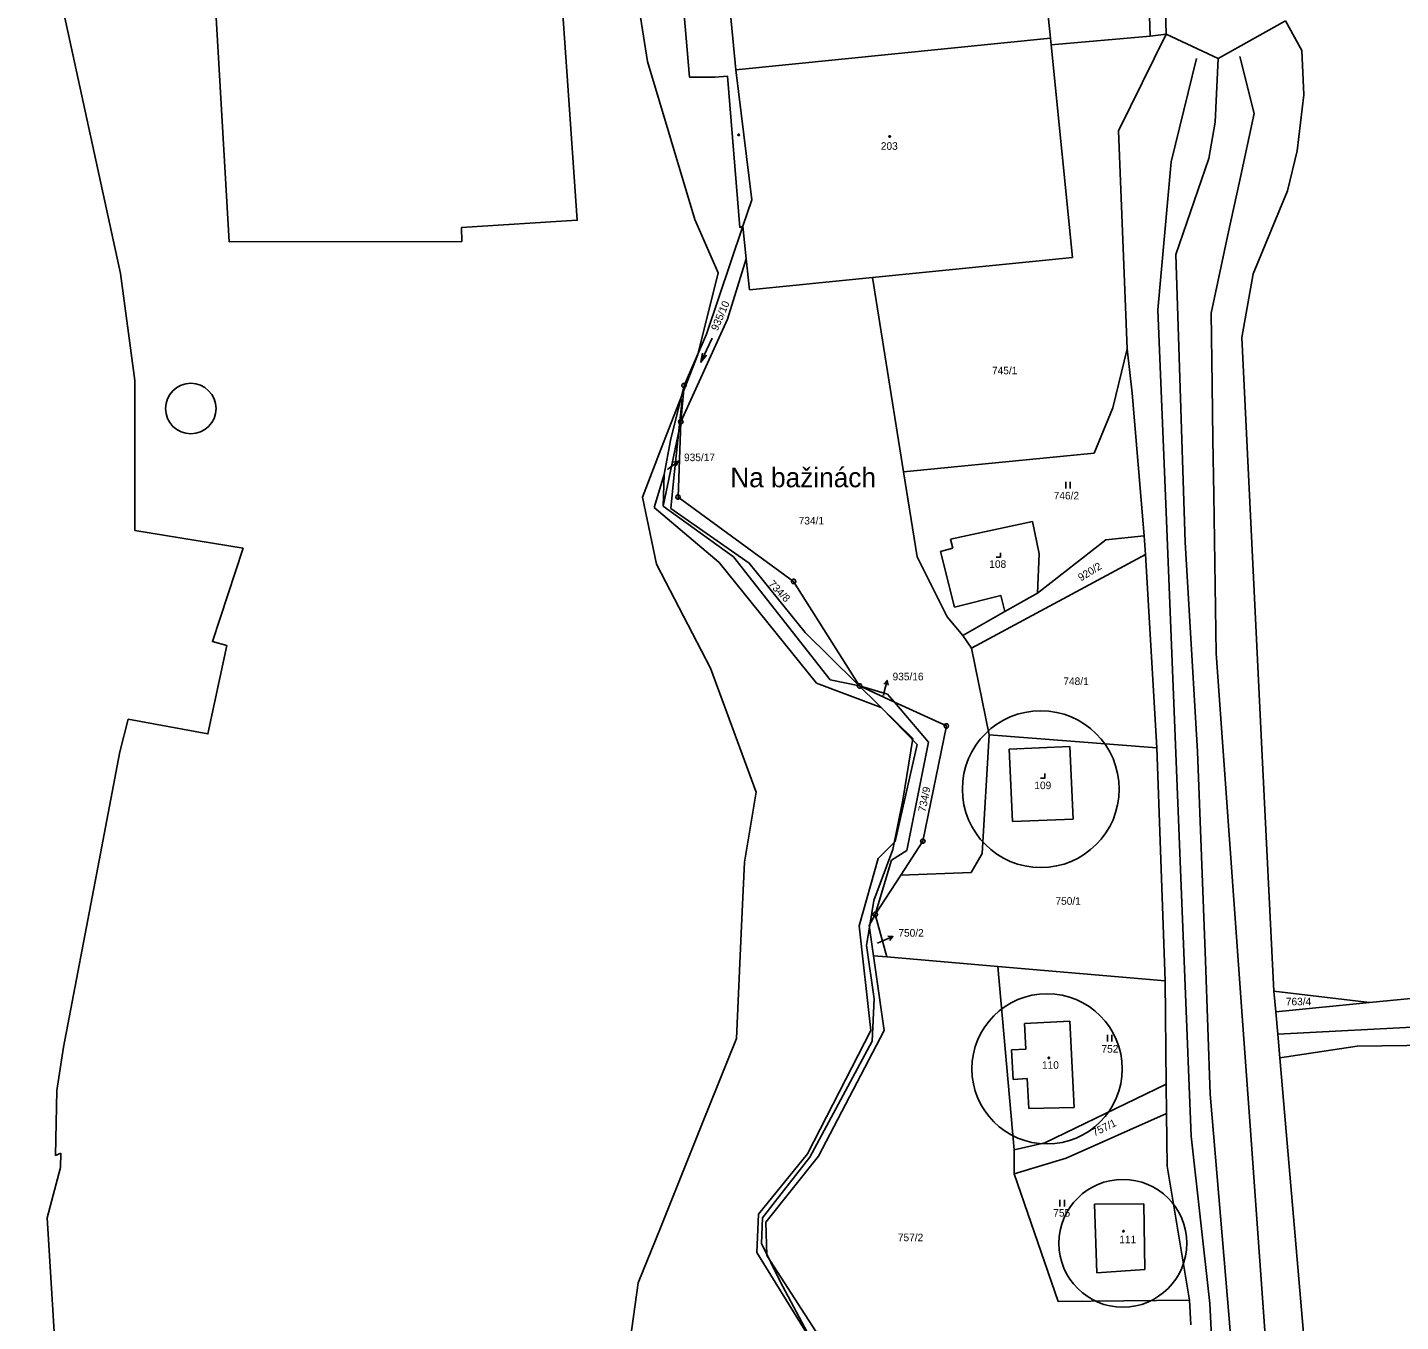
# Model space of a CAD drawing. Extents: x -580551 to -575069, y -1073031 to -1067931.
# Drawn here: x -578671.5 to -578363.2, y -1071557 to -1071266.5 of the extents above; entities that cross this region are included whole.
import ezdxf

# ---------------------------------------------------------------- set-up
doc = ezdxf.new("R2010")
doc.units = 0
for name, color, linetype in [('Druh pozemku', 7, 'Continuous'), ('Geodetické body', 7, 'Continuous'), ('Hranice státní', 7, 'Continuous'), ('Hranice z rastru', 7, 'Continuous'), ('Katastrální hranice', 7, 'Continuous'), ('Názvosloví', 7, 'Continuous'), ('Parcela', 7, 'Continuous'), ('Parcelní číslo', 7, 'Continuous'), ('Parcelní číslo_stavba', 7, 'Continuous'), ('Pomocná vrstva', 7, 'Continuous'), ('SR - hranice státu', 7, 'Continuous'), ('stavební parcely', 7, 'Continuous')]:
    doc.layers.add(name, color=color, linetype=linetype)

msp = doc.modelspace()

# ---------------------------------------------------------------- linework, layer by layer
at = {"layer": 'Druh pozemku'}
for p, q in [((-578517.744, -1071336.265), (-578520.296, -1071341.695)), ((-578438.37, -1071368.5), (-578438.37, -1071370)), ((-578437.37, -1071370), (-578437.37, -1071368.5)), ((-578429.01, -1071492.7), (-578429.01, -1071494.2)), ((-578428.01, -1071494.2), (-578428.01, -1071492.7)), ((-578439.7, -1071529.68), (-578439.7, -1071531.18)), ((-578438.7, -1071531.18), (-578438.7, -1071529.68))]:
    msp.add_line(p, q, dxfattribs=at)
for points in [[(-578511.72, -1071290.49), (-578511.63, -1071290.64), (-578511.72, -1071290.79), (-578511.9, -1071290.79), (-578511.99, -1071290.64), (-578511.9, -1071290.49)], [(-578477.81, -1071290.85), (-578477.72, -1071291), (-578477.81, -1071291.15), (-578477.99, -1071291.15), (-578478.08, -1071291), (-578477.99, -1071290.85)], [(-578442.1, -1071497.72), (-578442.01, -1071497.87), (-578442.1, -1071498.02), (-578442.28, -1071498.02), (-578442.37, -1071497.87), (-578442.28, -1071497.72)], [(-578425.35, -1071536.61), (-578425.26, -1071536.76), (-578425.35, -1071536.91), (-578425.53, -1071536.91), (-578425.62, -1071536.76), (-578425.53, -1071536.61)]]:
    msp.add_lwpolyline(points, close=True, dxfattribs=at)
for points in [[(-578518.993, -1071340.098), (-578520.296, -1071341.695), (-578519.898, -1071339.672)], [(-578454.04, -1071385.44), (-578453.04, -1071385.44), (-578453.04, -1071384.44)], [(-578444.05, -1071435.02), (-578443.05, -1071435.02), (-578443.05, -1071434.02)]]:
    msp.add_lwpolyline(points, dxfattribs=at)
at = {"layer": 'Geodetické body'}
for p, q in [((-578524.19, -1071346.92), (-578523.95, -1071346.92)), ((-578524.91, -1071355.06), (-578524.67, -1071355.06)), ((-578525.52, -1071371.95), (-578525.28, -1071371.95)), ((-578499.59, -1071390.89), (-578499.35, -1071390.89)), ((-578484.79, -1071414.36), (-578484.55, -1071414.36)), ((-578465.29, -1071423.34), (-578465.05, -1071423.34)), ((-578470.58, -1071449.22), (-578470.34, -1071449.22)), ((-578481.27, -1071465.65), (-578481.03, -1071465.65))]:
    msp.add_line(p, q, dxfattribs=at)
for points in [[(-578523.92, -1071346.44), (-578523.67, -1071346.62), (-578523.57, -1071346.91), (-578523.67, -1071347.2), (-578523.92, -1071347.38), (-578524.23, -1071347.38), (-578524.48, -1071347.2), (-578524.58, -1071346.91), (-578524.48, -1071346.62), (-578524.23, -1071346.44)], [(-578524.64, -1071354.58), (-578524.39, -1071354.76), (-578524.29, -1071355.05), (-578524.39, -1071355.34), (-578524.64, -1071355.52), (-578524.95, -1071355.52), (-578525.2, -1071355.34), (-578525.3, -1071355.05), (-578525.2, -1071354.76), (-578524.95, -1071354.58)], [(-578525.25, -1071371.47), (-578525, -1071371.65), (-578524.9, -1071371.94), (-578525, -1071372.23), (-578525.25, -1071372.41), (-578525.56, -1071372.41), (-578525.81, -1071372.23), (-578525.91, -1071371.94), (-578525.81, -1071371.65), (-578525.56, -1071371.47)], [(-578499.32, -1071390.41), (-578499.07, -1071390.59), (-578498.97, -1071390.88), (-578499.07, -1071391.17), (-578499.32, -1071391.35), (-578499.63, -1071391.35), (-578499.88, -1071391.17), (-578499.98, -1071390.88), (-578499.88, -1071390.59), (-578499.63, -1071390.41)], [(-578484.52, -1071413.88), (-578484.27, -1071414.06), (-578484.17, -1071414.35), (-578484.27, -1071414.64), (-578484.52, -1071414.82), (-578484.83, -1071414.82), (-578485.08, -1071414.64), (-578485.18, -1071414.35), (-578485.08, -1071414.06), (-578484.83, -1071413.88)], [(-578465.02, -1071422.86), (-578464.77, -1071423.04), (-578464.67, -1071423.33), (-578464.77, -1071423.62), (-578465.02, -1071423.8), (-578465.33, -1071423.8), (-578465.58, -1071423.62), (-578465.68, -1071423.33), (-578465.58, -1071423.04), (-578465.33, -1071422.86)], [(-578470.31, -1071448.74), (-578470.06, -1071448.92), (-578469.96, -1071449.21), (-578470.06, -1071449.5), (-578470.31, -1071449.68), (-578470.62, -1071449.68), (-578470.87, -1071449.5), (-578470.97, -1071449.21), (-578470.87, -1071448.92), (-578470.62, -1071448.74)], [(-578481, -1071465.17), (-578480.75, -1071465.35), (-578480.65, -1071465.64), (-578480.75, -1071465.93), (-578481, -1071466.11), (-578481.31, -1071466.11), (-578481.56, -1071465.93), (-578481.66, -1071465.64), (-578481.56, -1071465.35), (-578481.31, -1071465.17)]]:
    msp.add_lwpolyline(points, close=True, dxfattribs=at)
at = {"layer": 'Hranice státní'}
for points in [[(-578626.17, -1071314.69), (-578631.39, -1071224.25), (-578664.54, -1071223.02), (-578671.45, -1071227.83), (-578669.19, -1071236.12), (-578650.54, -1071321.74)], [(-578552.47, -1071246.09), (-578552.3, -1071248.53), (-578550.21, -1071278.52), (-578548.05, -1071309.81), (-578573.99, -1071311.43)], [(-578573.99, -1071311.43), (-578573.95, -1071314.61), (-578626.17, -1071314.69)], [(-578647.35, -1071379.42), (-578647.36, -1071345.76), (-578650.54, -1071321.74)], [(-578655.932, -1071456.69), (-578650.69, -1071429.16), (-578648.82, -1071421.84), (-578630.96, -1071425.12), (-578626.72, -1071405.25), (-578629.93, -1071404.41), (-578623.05, -1071383.45), (-578647.35, -1071379.42)], [(-578663.98, -1071519.25), (-578665.15, -1071519.72), (-578664.84, -1071505.19), (-578663.37, -1071495.46), (-578655.932, -1071456.69)], [(-578664.84, -1071569.07), (-578667.05, -1071533.73), (-578664.06, -1071522.44), (-578663.98, -1071519.25)]]:
    msp.add_lwpolyline(points, dxfattribs=at)
at = {"layer": 'Hranice z rastru'}
for points in [[(-578566.72, -1070947.779), (-578583.48, -1070998.532), (-578590.876, -1071020.93), (-578592.521, -1071043.374), (-578590.032, -1071060.419), (-578576.797, -1071098.705), (-578560.811, -1071139.089), (-578544.825, -1071179.473), (-578532.639, -1071204.254), (-578528.184, -1071216.579), (-578534.736, -1071226.806), (-578537.749, -1071239.524), (-578532.246, -1071274.139), (-578521.632, -1071309.672), (-578516.391, -1071321.603), (-578520.977, -1071339.96), (-578529.232, -1071361.069)], [(-578524.515, -1071350.056), (-578526.349, -1071367.625), (-578527.069, -1071374.513), (-578509.446, -1071386.768), (-578496.867, -1071402.371), (-578479.81, -1071419.16), (-578472.686, -1071426.172), (-578474.984, -1071440.002)], [(-578529.232, -1071361.069), (-578533.425, -1071371.952), (-578530.281, -1071387.03), (-578518.094, -1071410.369), (-578507.874, -1071438.166), (-578510.494, -1071453.9), (-578511.15, -1071468.192), (-578512.309, -1071493.474), (-578520.06, -1071512.771), (-578529.38, -1071535.973), (-578534.352, -1071548.353), (-578536.177, -1071561.284), (-578541.549, -1071612.813), (-578546.922, -1071632.874), (-578552.556, -1071647.953), (-578557.667, -1071673.258), (-578558.191, -1071704.464), (-578562.52, -1071736.58)], [(-578474.984, -1071440.002), (-578477.225, -1071451.09), (-578481.493, -1071462.479), (-578483.14, -1071472.593), (-578481.418, -1071484.581), (-578481.867, -1071494.097), (-578487.333, -1071504.286), (-578495.834, -1071520.133), (-578503.582, -1071530.06), (-578506.476, -1071533.768), (-578506.652, -1071539.5), (-578502.458, -1071548.042), (-578487.932, -1071575.464), (-578485.686, -1071582.057), (-578485.462, -1071587.152)]]:
    msp.add_lwpolyline(points, dxfattribs=at)
at = {"layer": 'Katastrální hranice'}
for p, q in [((-578512.42, -1071276.06), (-578514.34, -1071256.25)), ((-578508.88, -1071305.23), (-578512.42, -1071276.06)), ((-578510.86, -1071311.12), (-578508.88, -1071305.23)), ((-578519.01, -1071335.4), (-578510.86, -1071311.12)), ((-578524.07, -1071346.92), (-578519.01, -1071335.4)), ((-578527.09, -1071359.26), (-578524.07, -1071346.92)), ((-578528.52, -1071366.9), (-578527.09, -1071359.26)), ((-578530.79, -1071374.27), (-578528.52, -1071366.9)), ((-578516.17, -1071386.61), (-578530.79, -1071374.27)), ((-578494.3, -1071413.72), (-578516.17, -1071386.61)), ((-578479.81, -1071419.16), (-578494.3, -1071413.72)), ((-578471.75, -1071427.49), (-578479.81, -1071419.16)), ((-578476.66, -1071449.27), (-578471.75, -1071427.49)), ((-578480.48, -1071453.05), (-578476.66, -1071449.27)), ((-578484.74, -1071468.22), (-578480.48, -1071453.05)), ((-578482.17, -1071491.71), (-578484.74, -1071468.22)), ((-578496.32, -1071519.41), (-578482.17, -1071491.71)), ((-578507.37, -1071532.95), (-578496.32, -1071519.41)), ((-578507.7, -1071541.54), (-578507.37, -1071532.95)), ((-578495.41, -1071561.51), (-578507.7, -1071541.54))]:
    msp.add_line(p, q, dxfattribs=at)
at = {"layer": 'Parcela'}
for p, q in [((-578446.68, -1071221.87), (-578441.84, -1071268.91)), ((-578417.28, -1071222.89), (-578415.83, -1071268.01)), ((-578420.39, -1071237.61), (-578419.43, -1071268.52)), ((-578385.4, -1071271.68), (-578389.04, -1071265.06)), ((-578512.42, -1071276.06), (-578441.84, -1071268.91)), ((-578441.84, -1071268.91), (-578441.69, -1071270.4)), ((-578419.43, -1071268.52), (-578441.69, -1071270.4)), ((-578415.83, -1071268.01), (-578426.53, -1071289.74)), ((-578415.83, -1071268.01), (-578419.43, -1071268.52)), ((-578415.83, -1071268.01), (-578404.15, -1071273.47)), ((-578441.69, -1071270.4), (-578436.87, -1071318.14)), ((-578384.97, -1071281.68), (-578385.4, -1071271.68)), ((-578404.15, -1071273.47), (-578404.81, -1071287.76)), ((-578386.42, -1071294.26), (-578384.97, -1071281.68)), ((-578404.81, -1071287.76), (-578406.28, -1071295.97)), ((-578426.53, -1071289.74), (-578424.62, -1071338.68)), ((-578388.59, -1071303.21), (-578386.42, -1071294.26)), ((-578406.28, -1071295.97), (-578413.7, -1071317.47)), ((-578396.33, -1071321.84), (-578388.59, -1071303.21)), ((-578510.1, -1071318.51), (-578510.86, -1071311.12)), ((-578514.34, -1071332.04), (-578510.1, -1071318.51)), ((-578509.39, -1071325.42), (-578510.1, -1071318.51)), ((-578436.87, -1071318.14), (-578481.75, -1071322.65)), ((-578413.7, -1071317.47), (-578411.56, -1071382.05)), ((-578398.83, -1071336.15), (-578396.33, -1071321.84)), ((-578481.75, -1071322.65), (-578509.39, -1071325.42)), ((-578474.78, -1071366.32), (-578481.75, -1071322.65)), ((-578524.79, -1071355.06), (-578514.34, -1071332.04)), ((-578394.3, -1071430.07), (-578398.83, -1071336.15)), ((-578427.8, -1071351.93), (-578424.62, -1071338.68)), ((-578424.62, -1071338.68), (-578423.49, -1071348.61)), ((-578524.79, -1071355.06), (-578524.07, -1071346.92)), ((-578423.49, -1071348.61), (-578420.82, -1071380.64)), ((-578432, -1071362.11), (-578427.8, -1071351.93)), ((-578524.79, -1071355.06), (-578528.73, -1071373.96)), ((-578525.4, -1071371.95), (-578524.79, -1071355.06)), ((-578474.78, -1071366.32), (-578432, -1071362.11)), ((-578528.52, -1071366.9), (-578528.73, -1071373.96)), ((-578471.74, -1071385.37), (-578474.78, -1071366.32)), ((-578512.93, -1071385.39), (-578528.73, -1071373.96)), ((-578499.47, -1071390.89), (-578525.4, -1071371.95)), ((-578464.27, -1071381.37), (-578445.87, -1071377.46)), ((-578445.87, -1071377.46), (-578444.34, -1071384.67)), ((-578420.82, -1071380.64), (-578429.37, -1071381.57)), ((-578420.82, -1071380.64), (-578420.47, -1071384.83)), ((-578466.5, -1071384.14), (-578463.75, -1071383.46)), ((-578463.75, -1071383.46), (-578464.27, -1071381.37)), ((-578429.37, -1071381.57), (-578444.75, -1071393.53)), ((-578411.56, -1071382.05), (-578408.83, -1071429.07)), ((-578491.25, -1071412.97), (-578512.93, -1071385.39)), ((-578471.74, -1071385.37), (-578464.99, -1071398.84)), ((-578463.36, -1071396.65), (-578466.5, -1071384.14)), ((-578459.52, -1071405.85), (-578420.47, -1071384.83)), ((-578444.34, -1071384.67), (-578444.75, -1071393.53)), ((-578420.47, -1071384.83), (-578417.96, -1071428.23)), ((-578484.95, -1071413.91), (-578499.47, -1071390.89)), ((-578452.94, -1071394.04), (-578463.36, -1071396.65)), ((-578452.03, -1071397.67), (-578452.94, -1071394.04)), ((-578444.75, -1071393.53), (-578452.03, -1071397.67)), ((-578464.99, -1071398.84), (-578461.49, -1071403.05)), ((-578452.03, -1071397.67), (-578461.49, -1071403.05)), ((-578461.49, -1071403.05), (-578459.52, -1071405.85)), ((-578459.52, -1071405.85), (-578455.6, -1071425.33)), ((-578484.67, -1071414.36), (-578491.25, -1071412.97)), ((-578484.67, -1071414.36), (-578484.95, -1071413.91)), ((-578476.84, -1071417.96), (-578484.67, -1071414.36)), ((-578478.37, -1071416.16), (-578484.67, -1071414.36)), ((-578476.84, -1071417.96), (-578478.37, -1071416.16)), ((-578465.17, -1071423.34), (-578476.84, -1071417.96)), ((-578469.17, -1071426.96), (-578476.84, -1071417.96)), ((-578470.46, -1071449.22), (-578465.17, -1071423.34)), ((-578474.04, -1071451.28), (-578469.17, -1071426.96)), ((-578455.6, -1071425.33), (-578457.13, -1071451.98)), ((-578455.6, -1071425.33), (-578417.96, -1071428.23)), ((-578437.49, -1071427.98), (-578451.08, -1071428.58)), ((-578451.08, -1071428.58), (-578450.37, -1071444.79)), ((-578436.74, -1071444.29), (-578437.49, -1071427.98)), ((-578417.96, -1071428.23), (-578416.08, -1071480.56)), ((-578408.83, -1071429.07), (-578407, -1071476.06)), ((-578391.64, -1071482.88), (-578394.3, -1071430.07)), ((-578450.37, -1071444.79), (-578436.74, -1071444.29)), ((-578477.48, -1071453.43), (-578474.04, -1071451.28)), ((-578475.43, -1071456.86), (-578470.46, -1071449.22)), ((-578481.15, -1071465.65), (-578477.48, -1071453.43)), ((-578457.13, -1071451.98), (-578459.65, -1071456.26)), ((-578481.15, -1071465.65), (-578475.43, -1071456.86)), ((-578459.65, -1071456.26), (-578475.43, -1071456.86)), ((-578481.15, -1071465.65), (-578482.53, -1071468.14)), ((-578478.51, -1071475.19), (-578481.15, -1071465.65)), ((-578482.53, -1071468.14), (-578481.56, -1071474.93)), ((-578478.51, -1071475.19), (-578481.56, -1071474.93)), ((-578481.56, -1071474.93), (-578479.16, -1071491.71)), ((-578453.66, -1071477.33), (-578478.51, -1071475.19)), ((-578407, -1071476.06), (-578405.99, -1071505.99)), ((-578416.08, -1071480.56), (-578453.66, -1071477.33)), ((-578453.66, -1071477.33), (-578449.94, -1071518.45)), ((-578416.08, -1071480.56), (-578415.81, -1071503.77)), ((-578370.22, -1071485.41), (-578337.23, -1071482.16)), ((-578370.22, -1071485.41), (-578391.64, -1071482.88)), ((-578391.24, -1071487.47), (-578391.64, -1071482.88)), ((-578391.24, -1071487.47), (-578370.22, -1071485.41)), ((-578255.84, -1071485.26), (-578390.8, -1071492.55)), ((-578390.8, -1071492.55), (-578391.24, -1071487.47)), ((-578437.44, -1071489.62), (-578447.63, -1071490.1)), ((-578447.63, -1071490.1), (-578447.34, -1071495.89)), ((-578436.53, -1071508.97), (-578437.44, -1071489.62)), ((-578479.16, -1071491.71), (-578493.9, -1071519.9)), ((-578390.34, -1071497.85), (-578390.8, -1071492.55)), ((-578338.79, -1071494.68), (-578373, -1071495.22)), ((-578447.34, -1071495.89), (-578450.53, -1071496.05)), ((-578450.53, -1071496.05), (-578450.2, -1071502.66)), ((-578373, -1071495.22), (-578390.34, -1071497.85)), ((-578384.36, -1071566.86), (-578390.34, -1071497.85)), ((-578450.2, -1071502.66), (-578447.02, -1071502.5)), ((-578447.02, -1071502.5), (-578446.69, -1071509.17)), ((-578415.81, -1071503.77), (-578443.06, -1071516.92)), ((-578415.81, -1071503.77), (-578415.78, -1071510.3)), ((-578405.99, -1071505.99), (-578401.72, -1071556.32)), ((-578446.69, -1071509.17), (-578436.53, -1071508.97)), ((-578415.78, -1071510.3), (-578438.31, -1071520.35)), ((-578415.78, -1071510.3), (-578415.65, -1071522.12)), ((-578449.98, -1071523.89), (-578449.94, -1071518.45)), ((-578443.06, -1071516.92), (-578449.94, -1071518.45)), ((-578493.9, -1071519.9), (-578505.72, -1071534.73)), ((-578438.31, -1071520.35), (-578449.98, -1071523.89)), ((-578415.65, -1071522.12), (-578410.63, -1071552.24)), ((-578449.98, -1071523.89), (-578440.12, -1071552.5)), ((-578431.95, -1071530.69), (-578420.85, -1071530.6)), ((-578431.41, -1071546.12), (-578431.95, -1071530.69)), ((-578420.85, -1071530.6), (-578420.66, -1071545.32)), ((-578505.72, -1071534.73), (-578505.51, -1071542.17)), ((-578505.51, -1071542.17), (-578493.73, -1071560.37)), ((-578420.66, -1071545.32), (-578431.41, -1071546.12)), ((-578440.12, -1071552.5), (-578410.63, -1071552.24)), ((-578410.63, -1071552.24), (-578410.33, -1071557.74)), ((-578401.72, -1071556.32), (-578388.66, -1071725.04))]:
    msp.add_line(p, q, dxfattribs=at)
at = {"layer": 'Parcelní číslo'}
msp.add_lwpolyline([(-578399.327, -1071273.026), (-578396.116, -1071285.875), (-578399.327, -1071300.79), (-578401.977, -1071313.104), (-578405.754, -1071330.65), (-578405.518, -1071346.681), (-578405.336, -1071359.065), (-578405.154, -1071371.45), (-578404.63, -1071407.045), (-578401.62, -1071448.788), (-578398.61, -1071490.531), (-578396.984, -1071513.081), (-578392.613, -1071573.689)], dxfattribs=at)
at = {"layer": 'Parcelní číslo_stavba'}
for points in [[(-578409.001, -1071273.487), (-578414.734, -1071296.662), (-578417.715, -1071329.933), (-578415.88, -1071375.365), (-578411.662, -1071479.827), (-578410.225, -1071515.418)], [(-578410.225, -1071515.418), (-578406.02, -1071552.962), (-578402.58, -1071620.881), (-578395.931, -1071690.176), (-578392.62, -1071724.672), (-578386.469, -1071788.769), (-578388.134, -1071812.704), (-578398.682, -1071862.955), (-578406.937, -1071887.277), (-578424.135, -1071918.941), (-578437.435, -1071934.315), (-578491.323, -1071986.63)]]:
    msp.add_lwpolyline(points, dxfattribs=at)
at = {"layer": 'Pomocná vrstva'}
for p, q in [((-578525.313, -1071363.893), (-578527.7, -1071365.71)), ((-578527.74, -1071365.74), (-578527.7, -1071365.71)), ((-578478.491, -1071413.093), (-578479.19, -1071416.01)), ((-578479.31, -1071416.51), (-578479.19, -1071416.01)), ((-578480.67, -1071472.08), (-578479.96, -1071471.78)), ((-578477.191, -1071470.627), (-578479.96, -1071471.78))]:
    msp.add_line(p, q, dxfattribs=at)
for points in [[(-578526.411, -1071364.101), (-578525.313, -1071363.893), (-578525.806, -1071364.897)], [(-578479.21, -1071413.949), (-578478.491, -1071413.093), (-578478.238, -1071414.182)], [(-578478.306, -1071470.55), (-578477.191, -1071470.627), (-578477.921, -1071471.473)]]:
    msp.add_lwpolyline(points, dxfattribs=at)
at = {"layer": 'SR - hranice státu'}
msp.add_line((-578517.09, -1071277.68), (-578514.33, -1071277.47), dxfattribs=at)
for points in [[(-578513.93, -1071228.71), (-578515.74, -1071230.46), (-578526.81, -1071231.26), (-578522.85, -1071277.67), (-578517.09, -1071277.68)], [(-578389.04, -1071265.06), (-578404.15, -1071273.47), (-578415.83, -1071268.01), (-578426.53, -1071289.74)], [(-578514.33, -1071277.47), (-578511.58, -1071311.42), (-578510.86, -1071311.12)], [(-578426.53, -1071289.74), (-578424.62, -1071338.68), (-578423.49, -1071348.61), (-578420.82, -1071380.64), (-578420.47, -1071384.83)], [(-578509.39, -1071325.42), (-578510.1, -1071318.51), (-578510.86, -1071311.12)], [(-578420.47, -1071384.83), (-578459.52, -1071405.85), (-578461.49, -1071403.05), (-578464.99, -1071398.84), (-578471.74, -1071385.37), (-578474.78, -1071366.32), (-578481.75, -1071322.65), (-578509.39, -1071325.42)]]:
    msp.add_lwpolyline(points, dxfattribs=at)
at = {"layer": 'stavební parcely'}
for centre, radius in [((-578634.78, -1071352.079), 5.662), ((-578443.99, -1071437.52), 17.597), ((-578442.58, -1071500.3), 16.866), ((-578425.56, -1071539.47), 14.352)]:
    msp.add_circle(centre, radius, dxfattribs=at)

# ---------------------------------------------------------------- texts
at = {"layer": 'Názvosloví'}
msp.add_text('Na bažinách', height=4.4, dxfattribs=at).set_placement((-578513.692, -1071369.75))
at = {"layer": 'Parcelní číslo'}
for s, rotation, p in [('935/10', 66.69229, (-578516.544, -1071334.769)), ('920/2', 31.39809, (-578434.987, -1071390.908)), ('734/8', 313.86628, (-578505.23, -1071391.603)), ('734/9', 78.09415, (-578469.883, -1071442.745)), ('757/1', 26.12687, (-578431.948, -1071515.516))]:
    msp.add_text(s, height=1.7, rotation=rotation, dxfattribs=at).set_placement(p)
for s, height, p in [('745/1', 1.7, (-578454.938, -1071344.39)), ('935/17', 0.1, (-578527.968, -1071365.74)), ('746/2', 1.7, (-578441.089, -1071372.48)), ('734/1', 1.7, (-578498.334, -1071378.1)), ('748/1', 1.7, (-578438.92, -1071414.15)), ('935/16', 0.1, (-578479.54, -1071416.51)), ('750/1', 1.7, (-578440.692, -1071463.47)), ('750/2', 0.1, (-578480.878, -1071472.08)), ('763/4', 1.7, (-578388.981, -1071486.04)), ('752', 1.7, (-578430.365, -1071496.67)), ('755', 1.7, (-578441.182, -1071533.48)), ('757/2', 1.7, (-578476.065, -1071539))]:
    msp.add_text(s, height=height, dxfattribs=at).set_placement(p)
at = {"layer": 'Parcelní číslo_stavba'}
for s, p in [('203', (-578479.89, -1071294)), ('108', (-578455.549, -1071387.84)), ('109', (-578445.431, -1071437.52)), ('110', (-578443.714, -1071500.3)), ('111', (-578426.363, -1071539.47))]:
    msp.add_text(s, height=1.7, dxfattribs=at).set_placement(p)
at = {"layer": 'Pomocná vrstva'}
for s, p in [('935/17', (-578524.073, -1071363.89)), ('935/16', (-578477.253, -1071413.09)), ('750/2', (-578475.953, -1071470.63))]:
    msp.add_text(s, height=1.7, dxfattribs=at).set_placement(p)

doc.saveas('drawing.dxf')
